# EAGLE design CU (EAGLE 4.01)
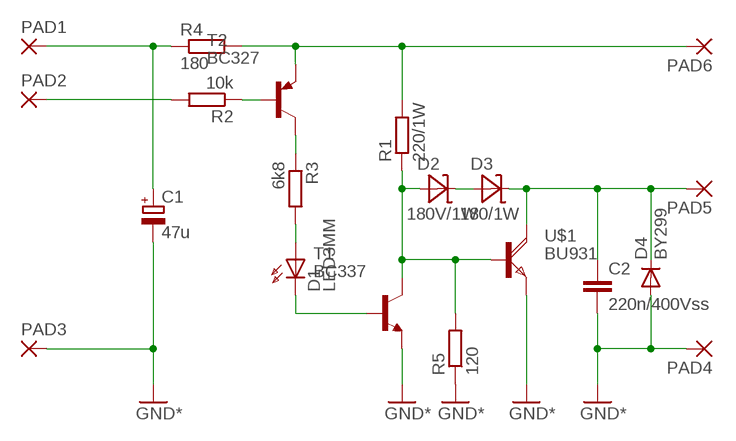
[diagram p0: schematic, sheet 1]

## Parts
C1  47u  CPOL-EUE2.5-6  [E2,5-6]
C2  220n/400Vss  C-EU225-062X268  [C225-062X268]
D1  LED3MM  [LED3MM]
D2  180V/1W  ZDIODE-12.5  [ZDIO12.5]
D3  180/1W  ZDIODE-12.5  [ZDIO12.5]
D4  BY299  1N4004  [DO41-10]
PAD1  3,81/1,4  [3,81/1,4]
PAD2  3,81/1,4  [3,81/1,4]
PAD3  3,81/1,4  [3,81/1,4]
PAD4  3,81/1,4  [3,81/1,4]
PAD5  3,81/1,4  [3,81/1,4]
PAD6  3,81/1,4  [3,81/1,4]
R1  220/1W  R-EU_0411/12  [0411/12]
R2  10k  R-EU_0207/10  [0207/10]
R3  6k8  R-EU_0207/10  [0207/10]
R4  180  R-EU_0207/10  [0207/10]
R5  120  R-EU_0207/10  [0207/10]
T1  BC337  [TO92]
T2  BC327  [TO92]
U$1  BU931T  [TO220AH]

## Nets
GND: C1.- C2.1 D4.A PAD3.1(P) PAD4.1(P) R5.1 T1.1(E) U$1.E ; supply symbol labelled GND*
N$1: D2.A R1.1 R5.2 T1.3(C) U$1.B
N$2: R3.1 T2.3(C)
N$3: D1.A R3.2
N$4: D1.K(C) T1.2(B)
N$5: PAD2.1(P) R2.2
N$6: C1.+ PAD1.1(P) R4.1
N$8: R2.1 T2.2(B)
N$9: PAD6.1(P) R1.2 R4.2 T2.1(E)
N$11: D2.K(C) D3.A
N$12: C2.2 D3.K(C) D4.K(C) PAD5.1(P) U$1.C

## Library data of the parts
C1 = rcl:CPOL-EU: POLARIZED CAPACITOR, European symbol
C2 = rcl:C-EU: CAPACITOR, European symbol
D1 = led:LED3MM: LED
D2 D3 = diode:ZDIODE-: Z DIODE
D4 = diode:1N4004: DIODE
PAD1-PAD6 = wirepad:3,81/1,4: THROUGH-HOLE PAD
R1-R5 = rcl:R-EU_: RESISTOR, European symbol
T1 = transistor-npn:BC337: NPN TRANSISTOR
T2 = transistor-pnp:BC327: PNP TRANSISTOR
U$1 = transistor-power:BU931

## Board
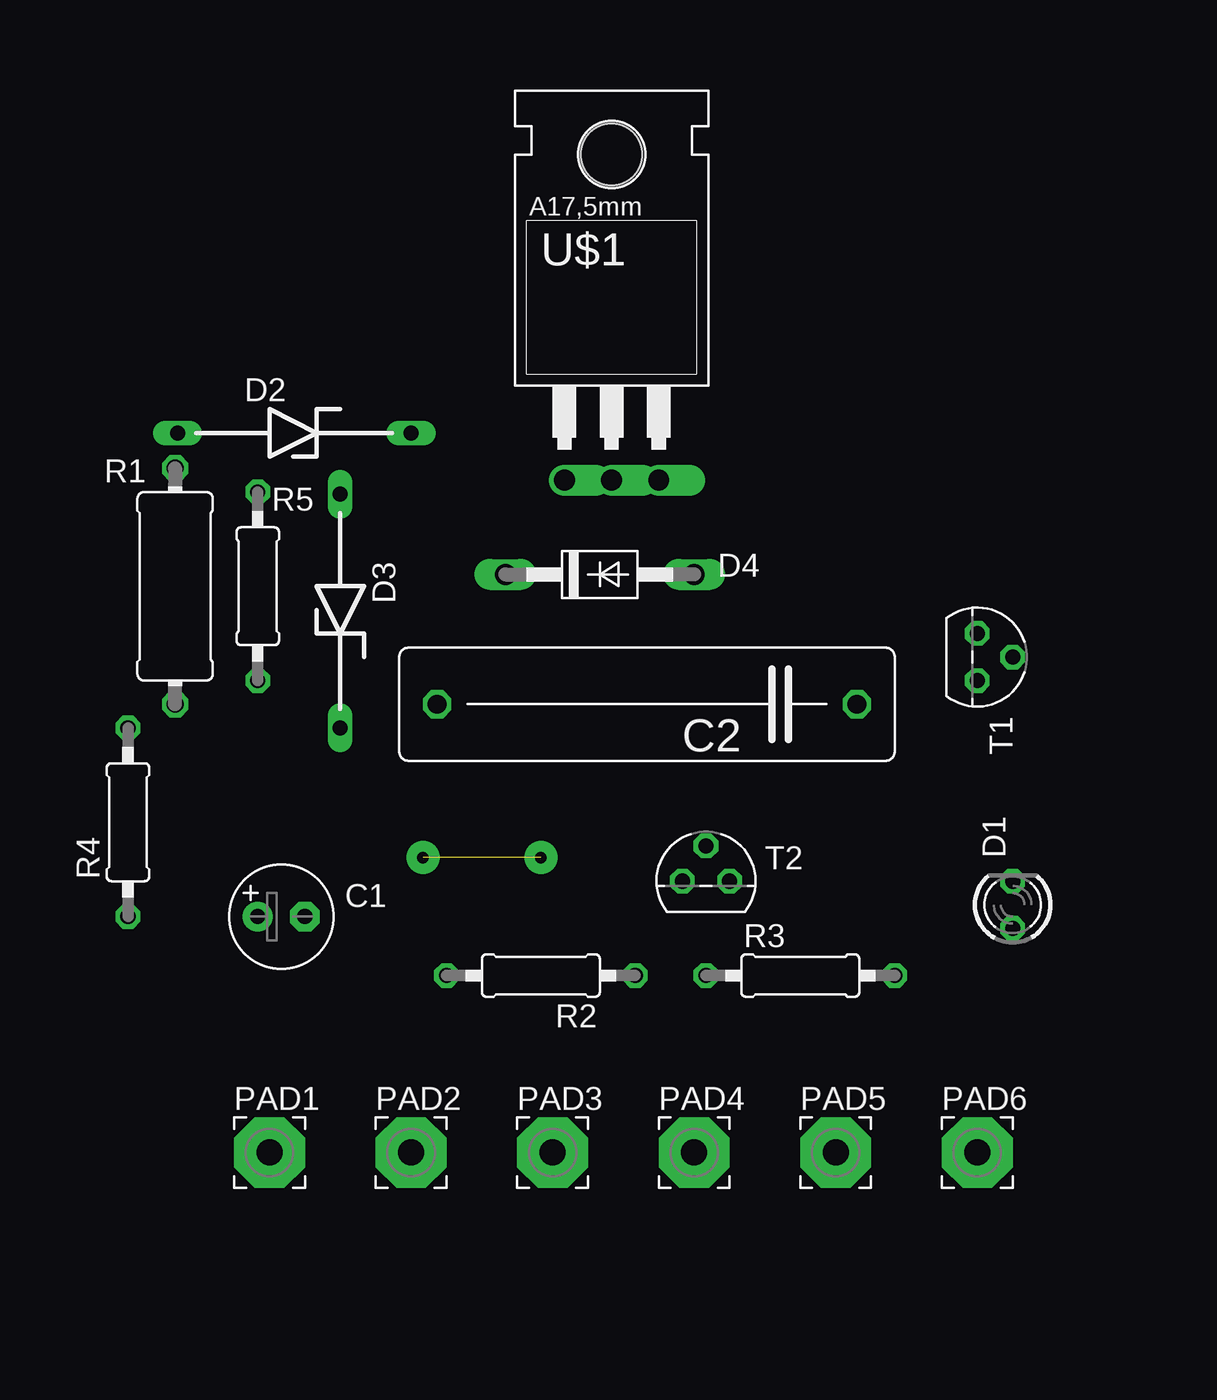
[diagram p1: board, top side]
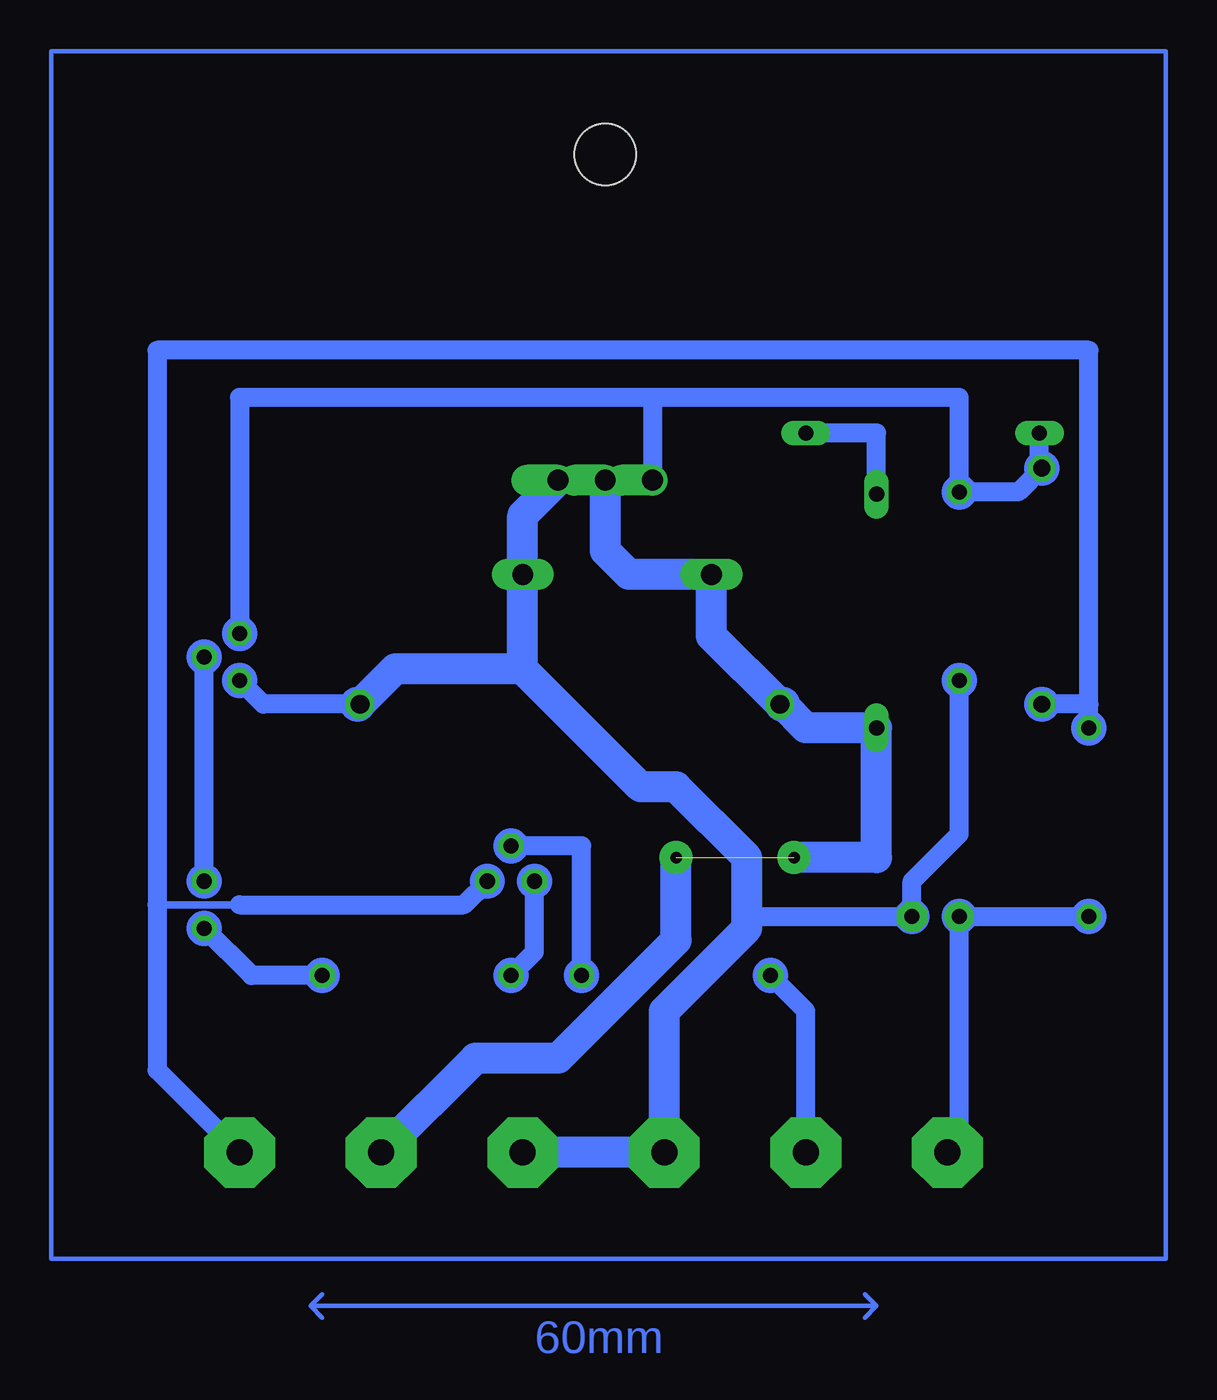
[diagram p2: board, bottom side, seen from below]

No outline drawn. Coordinates in mm, seen from the top.
Copper layers used: Bottom

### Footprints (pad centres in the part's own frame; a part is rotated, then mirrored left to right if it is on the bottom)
E2,5-6 = drill 0.813 pad 1.6 round: + -1.27,0 | drill 0.813 pad 1.6 octagon: - 1.27,0
C225-062X268 = drill 1.016 octagon: 1 -11.303,0; 2 11.303,0
LED3MM = drill 0.813 octagon: A -1.27,0; K 1.27,0
ZDIO12.5 = drill 0.813 long: A -6.223,0; K 6.35,0
DO41-10 = drill 1.118 long: A 5.08,0; K -5.08,0
3,81/1,4 = drill 1.397 pad 3.81 octagon: 1 0,0
0411/12 = drill 0.914 octagon: 1 -6.35,0; 2 6.35,0
0207/10 = drill 0.813 octagon: 1 -5.08,0; 2 5.08,0
TO92 = drill 0.813 octagon: 1 1.27,0; 2 0,1.905; 3 -1.27,0
TO220AH = drill 1.118 offset: B -2.54,-6.35; C 0,-6.35; E 2.54,-6.35 | hole 3.302: 0,11.176

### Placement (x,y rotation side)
C1  12.7,18.41 0 top
C2  32.38,29.84 180 top
D1  52.07,19.05 90 top
D2  13.34,44.45 0 top
D3  15.88,34.92 270 top
D4  29.84,36.83 0 top
PAD1  12.06,5.71 0 top
PAD2  19.68,5.71 0 top
PAD3  27.3,5.71 0 top
PAD4  34.92,5.71 0 top
PAD5  42.55,5.71 0 top
PAD6  50.16,5.71 0 top
R1  6.99,36.2 270 top
R2  26.67,15.24 180 top
R3  40.64,15.24 0 top
R4  4.45,23.5 90 top
R5  11.43,36.2 90 top
T1  50.16,32.38 270 top
T2  35.56,20.32 0 top
U$1  30.48,48.26 0 top

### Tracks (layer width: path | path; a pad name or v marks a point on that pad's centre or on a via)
GND
  Bottom 1.016: 22.86,18.41 C1.- 13.97,20.32 11.43,22.86 R5.1 | 43.81,29.84 C2.1 48.9,29.84 T1.1
  Bottom 1.676: PAD4.1 PAD3.1 27.3,13.34 22.86,17.78 22.86,18.41 22.86,21.59 26.67,25.4 28.57,25.4 34.92,31.75 | 34.92,31.75 D4.A 34.92,40.01 U$1.E | C2.1 41.78,31.75 34.92,31.75
N$1
  Bottom 1.016: D2.A 7.11,42.67 R1.1 8.26,41.27 R5.2 11.43,46.35 27.94,46.35 | 27.94,46.35 U$1.B | 27.94,46.35 50.16,46.35 T1.3
N$2
  Bottom 1.016: T2.3 34.29,16.51 R3.1
N$3
  Bottom 1.016: R3.2 49.53,15.24 D1.A
N$4
  Bottom 1.016: D1.K T1.2
N$5
  Bottom 1.016: R2.2 19.68,13.34 PAD2.1
N$6
  Bottom 1.016: PAD1.1 11.43,6.35 C1.+ R4.1
N$7
  Bottom 0.254: 0.31,0 0.31,65 60.31,65 60.31,0 0.31,0
N$8
  Bottom 1.016: T2.2 31.75,22.23 R2.1
N$9
  Bottom 0.406: 54.61,19.05 50.16,19.05
  Bottom 1.016: PAD6.1 54.61,10.16 54.61,19.05 54.61,48.9 4.45,48.9 4.45,29.84 | R4.2 4.45,29.84 | 4.45,29.84 R1.2 | T2.1 38.1,19.05 50.16,19.05
N$10
  Bottom 0.254: 15.88,-2.54 46.35,-2.54 | 46.35,-2.54 45.72,-1.91 | 46.35,-2.54 45.72,-3.17 | 16.51,-1.91 15.88,-2.54 | 15.88,-2.54 16.51,-3.17
N$11
  Bottom 1.016: D3.A 15.88,44.45 D2.K
N$12  (via drill 0.61 pad 1.78)  (1 unrouted)
  Bottom 1.676: PAD5.1 37.47,10.79 33.02,10.79 26.67,17.14 v26.67,21.59 | v20.32,21.59 15.88,21.59 D3.K 19.68,28.57 20.95,29.84 C2.2 24.77,33.53 D4.K 29.21,36.83 30.48,38.1 U$1.C
(copper drawn outside any net)
  shapes: Bottom circle x22

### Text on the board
Bottom: 60mm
